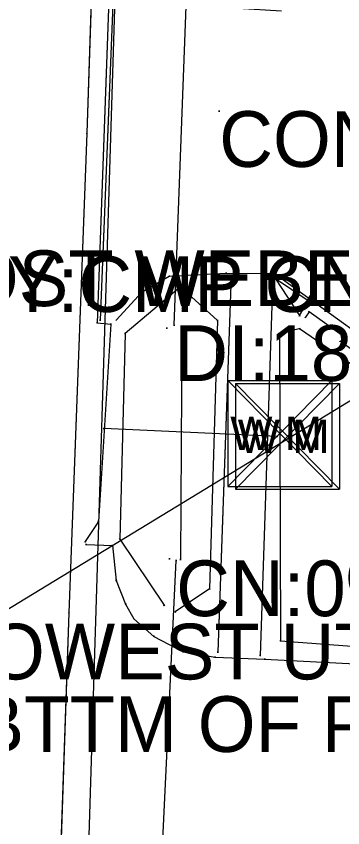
# Model space of a CAD drawing. Extents: x -99999 to 591807, y -99999 to 347168.
# Drawn here: x 591252.1 to 591281.4, y 320523.7 to 320596.6 of the extents above; entities that cross this region are included whole.
import ezdxf

# ---------------------------------------------------------------- set-up
doc = ezdxf.new("R2010")
doc.units = 0
for name, color, linetype in [('S_BREAKLINE', 7, 'Continuous'), ('S_CURB', 7, 'Continuous'), ('S_DITCHLINE', 7, 'Continuous'), ('S_DRG_PT_SYM', 7, 'Continuous'), ('S_DRIVEWAY', 7, 'Continuous'), ('S_EDGE_CONCRETE', 7, 'Continuous'), ('S_EDGE_PAVEMENT', 7, 'Continuous'), ('S_ELECTRIC_UTILITIES_ANNOT', 7, 'Continuous'), ('S_FENCE_ANNOT', 7, 'Continuous'), ('S_GRD_PT_SYM', 7, 'Continuous'), ('S_MSC_PT_SYM', 7, 'Continuous'), ('S_PARKING', 7, 'Continuous'), ('S_RDW_PT_SYM', 7, 'Continuous'), ('S_SHOULDER', 7, 'Continuous'), ('S_SIDE_DRAIN', 7, 'Continuous'), ('S_SIDE_DRAIN_ANNOT', 7, 'Continuous'), ('S_SIDEWALK', 7, 'Continuous'), ('S_SURVEY_TEXT_ANNOT', 7, 'Continuous'), ('S_UTL_PT_SYM', 7, 'Continuous'), ('S_WATER_UTILITIES', 7, 'Continuous')]:
    doc.layers.add(name, color=color, linetype=linetype)

msp = doc.modelspace()

# ---------------------------------------------------------------- linework, layer by layer
at = {"layer": 'S_BREAKLINE'}
for points in [[(591266.839, 320572.285), (591261.882, 320568.086), (591261.392, 320549.643), (591265.367, 320543.692)], [(591266.839, 320572.285), (591270.168, 320569.252), (591269.438, 320545.156), (591266.363, 320543.095)], [(591392.216, 320558.69), (591356.086, 320560.306), (591322.995, 320561.907), (591285.524, 320563.047), (591277.542, 320568.519), (591275.731, 320568.114), (591275.832, 320540.511), (591286.618, 320539.681), (591297.842, 320540.2), (591300.027, 320556.655), (591345.447, 320554.744), (591401.345, 320551.999)]]:
    msp.add_lwpolyline(points, dxfattribs=at)
at = {"layer": 'S_CURB'}
for points in [[(591281.353, 320567.898), (591278.386, 320570.023), (591278.072, 320569.548)], [(591281.353, 320567.898), (591278.386, 320570.023), (591278.072, 320569.548)], [(591407.479, 320558.411), (591363.839, 320560.323), (591322.914, 320562.301), (591285.893, 320563.966), (591281.187, 320567.394)], [(591407.479, 320558.411), (591385.659, 320559.367), (591363.839, 320560.323), (591343.376, 320561.312), (591322.914, 320562.301), (591304.404, 320563.134), (591285.893, 320563.966), (591281.187, 320567.394)], [(591407.501, 320558.912), (591363.862, 320560.823), (591322.937, 320562.802), (591286.066, 320564.459), (-99999, -99999)]]:
    msp.add_lwpolyline(points, dxfattribs=at)
at = {"layer": 'S_DITCHLINE'}
msp.add_lwpolyline([(591266.954, 320568.142), (591266.834, 320547.806)], dxfattribs=at)
msp.add_lwpolyline([(591266.954, 320568.142), (591266.834, 320547.806)], dxfattribs=at)
at = {"layer": 'S_DRG_PT_SYM'}
for points in [[(591266.286, 320568.827), (591266.286, 320568.877), (591266.286, 320568.827), (591266.236, 320568.827), (591266.286, 320568.827), (591266.286, 320568.777), (591266.286, 320568.827), (591266.336, 320568.827)], [(591266.449, 320547.719), (591266.449, 320547.769), (591266.449, 320547.719), (591266.399, 320547.719), (591266.449, 320547.719), (591266.449, 320547.669), (591266.449, 320547.719), (591266.499, 320547.719)]]:
    msp.add_lwpolyline(points, dxfattribs=at)
at = {"layer": 'S_DRIVEWAY'}
for points in [[(591275.923, 320597.03), (591271.994, 320597.253), (591266.956, 320597.82), (591264.475, 320599.333), (591263.245, 320601.023), (591262.616, 320602.121), (591260.941, 320602.14), (591259.624, 320569.278)], [(591275.923, 320597.03), (591271.994, 320597.253), (591266.956, 320597.82), (591264.475, 320599.333), (591263.245, 320601.023), (591262.616, 320602.121), (591260.941, 320602.14), (591260.282, 320585.709), (591259.624, 320569.278)], [(591261.069, 320569.288), (591263.4, 320571.823), (591265.823, 320573.221), (591270.933, 320573.516), (591275.152, 320573.478)], [(591261.069, 320569.288), (591263.4, 320571.823), (591265.823, 320573.221), (591270.933, 320573.516), (591275.152, 320573.478)], [(591258.362, 320549.144), (591260.745, 320549.059), (591261.061, 320545.933), (591261.907, 320543.789), (591262.648, 320542.475), (591264.456, 320540.899), (591267.082, 320539.519), (591269.942, 320539.026), (591274.417, 320538.861), (591285.436, 320538.297)], [(591258.362, 320549.144), (591260.745, 320549.059), (591261.061, 320545.933), (591261.907, 320543.789), (591262.648, 320542.475), (591264.456, 320540.899), (591267.082, 320539.519), (591269.942, 320539.026), (591274.417, 320538.861), (591285.436, 320538.297)]]:
    msp.add_lwpolyline(points, dxfattribs=at)
at = {"layer": 'S_EDGE_CONCRETE'}
msp.add_lwpolyline([(591275.36, 320573.004), (591277.536, 320569.699), (591278.31, 320571.012), (591275.36, 320573.004)], dxfattribs=at)
msp.add_lwpolyline([(591275.36, 320573.004), (591277.536, 320569.699), (591278.31, 320571.012)], close=True, dxfattribs=at)
at = {"layer": 'S_EDGE_PAVEMENT'}
for points in [[(591276.464, 321095.169), (591275.056, 321053.597), (591273.291, 321005.346), (591272, 320957.38), (591270.852, 320912.706), (591269.626, 320868.123), (591267.967, 320823.163), (591266.366, 320784.972), (591264.567, 320741.355), (591263.052, 320704.522), (591261.343, 320660.719), (591259.642, 320623.868), (591258.44, 320586.063), (591256.824, 320543.024), (591255.332, 320500.726), (591253.745, 320460.208), (591252.238, 320423.96)], [(591259.041, 320604.965), (591258.44, 320586.063), (591257.632, 320564.544), (591256.824, 320543.024), (591256.078, 320521.875), (591255.332, 320500.726), (591254.539, 320480.467), (591253.745, 320460.208), (591252.991, 320442.084), (591252.238, 320423.96)]]:
    msp.add_lwpolyline(points, dxfattribs=at)
at = {"layer": 'S_GRD_PT_SYM'}
for points in [[(591266.839, 320572.285), (591266.871, 320572.247), (591266.839, 320572.285), (591266.877, 320572.317), (591266.839, 320572.285), (591266.807, 320572.323), (591266.839, 320572.285), (591266.801, 320572.253)], [(591266.839, 320572.285), (591266.873, 320572.322), (591266.839, 320572.285), (591266.802, 320572.319), (591266.839, 320572.285), (591266.805, 320572.248), (591266.839, 320572.285), (591266.876, 320572.251)], [(591270.168, 320569.252), (591270.218, 320569.25), (591270.168, 320569.252), (591270.17, 320569.302), (591270.168, 320569.252), (591270.118, 320569.253), (591270.168, 320569.252), (591270.167, 320569.202)], [(591265.604, 320568.574), (591265.604, 320568.624), (591265.604, 320568.574), (591265.554, 320568.574), (591265.604, 320568.574), (591265.604, 320568.524), (591265.604, 320568.574), (591265.654, 320568.574)], [(591277.542, 320568.519), (591277.553, 320568.47), (591277.542, 320568.519), (591277.59, 320568.53), (591277.542, 320568.519), (591277.531, 320568.568), (591277.542, 320568.519), (591277.493, 320568.508)], [(591261.882, 320568.086), (591261.932, 320568.084), (591261.882, 320568.086), (591261.883, 320568.136), (591261.882, 320568.086), (591261.832, 320568.087), (591261.882, 320568.086), (591261.88, 320568.036)], [(591266.954, 320568.142), (591267.004, 320568.142), (591266.954, 320568.142), (591266.954, 320568.192), (591266.954, 320568.142), (591266.904, 320568.142), (591266.954, 320568.142), (591266.954, 320568.092)], [(591275.731, 320568.114), (591275.781, 320568.114), (591275.731, 320568.114), (591275.731, 320568.164), (591275.731, 320568.114), (591275.682, 320568.114), (591275.731, 320568.114), (591275.732, 320568.064)], [(591261.392, 320549.643), (591261.434, 320549.671), (591261.392, 320549.643), (591261.365, 320549.685), (591261.392, 320549.643), (591261.351, 320549.616), (591261.392, 320549.643), (591261.42, 320549.602)], [(591265.845, 320547.877), (591265.845, 320547.927), (591265.845, 320547.877), (591265.795, 320547.877), (591265.845, 320547.877), (591265.845, 320547.827), (591265.845, 320547.877), (591265.895, 320547.877)], [(591266.834, 320547.806), (591266.884, 320547.806), (591266.834, 320547.806), (591266.834, 320547.856), (591266.834, 320547.806), (591266.784, 320547.807), (591266.834, 320547.806), (591266.834, 320547.756)], [(591269.438, 320545.156), (591269.466, 320545.115), (591269.438, 320545.156), (591269.48, 320545.184), (591269.438, 320545.156), (591269.41, 320545.198), (591269.438, 320545.156), (591269.397, 320545.128)], [(591265.367, 320543.692), (591265.408, 320543.72), (591265.367, 320543.692), (591265.339, 320543.734), (591265.367, 320543.692), (591265.325, 320543.664), (591265.367, 320543.692), (591265.395, 320543.651)], [(591266.363, 320543.095), (591266.391, 320543.053), (591266.363, 320543.095), (591266.404, 320543.123), (591266.363, 320543.095), (591266.335, 320543.137), (591266.363, 320543.095), (591266.321, 320543.067)], [(591275.832, 320540.511), (591275.835, 320540.561), (591275.832, 320540.511), (591275.782, 320540.515), (591275.832, 320540.511), (591275.828, 320540.461), (591275.832, 320540.511), (591275.881, 320540.507)]]:
    msp.add_lwpolyline(points, close=True, dxfattribs=at)
at = {"layer": 'S_MSC_PT_SYM'}
msp.add_lwpolyline([(591270.318, 320588.044), (591270.318, 320588.094), (591270.318, 320588.044), (591270.268, 320588.044), (591270.318, 320588.044), (591270.318, 320587.994), (591270.318, 320588.044), (591270.368, 320588.044)], dxfattribs=at)
for points in [[(591271.385, 320573.331), (591271.435, 320573.329), (591271.385, 320573.331), (591271.387, 320573.381), (591271.385, 320573.331), (591271.335, 320573.333), (591271.385, 320573.331), (591271.383, 320573.281)], [(591275.128, 320573.267), (591275.177, 320573.265), (591275.128, 320573.267), (591275.129, 320573.317), (591275.128, 320573.267), (591275.078, 320573.269), (591275.128, 320573.267), (591275.126, 320573.217)], [(591275.449, 320573.327), (591275.42, 320573.287), (591275.449, 320573.327), (591275.49, 320573.298), (591275.449, 320573.327), (591275.479, 320573.368), (591275.449, 320573.327), (591275.409, 320573.356)], [(591270.191, 320539.488), (591270.241, 320539.486), (591270.191, 320539.488), (591270.193, 320539.538), (591270.191, 320539.488), (591270.141, 320539.49), (591270.191, 320539.488), (591270.189, 320539.438)], [(591274.006, 320539.192), (591274.056, 320539.19), (591274.006, 320539.192), (591274.008, 320539.242), (591274.006, 320539.192), (591273.956, 320539.193), (591274.006, 320539.192), (591274.005, 320539.142)]]:
    msp.add_lwpolyline(points, close=True, dxfattribs=at)
at = {"layer": 'S_PARKING'}
for points in [[(591407.979, 320559.722), (591364.006, 320561.845), (591322.955, 320563.708), (591286.426, 320565.418), (591275.449, 320573.327)], [(591407.979, 320559.722), (591385.992, 320560.784), (591364.006, 320561.845), (591343.48, 320562.776), (591322.955, 320563.708), (591304.691, 320564.563), (591286.426, 320565.418), (591275.449, 320573.327)]]:
    msp.add_lwpolyline(points, dxfattribs=at)
at = {"layer": 'S_RDW_PT_SYM'}
for points in [[(591258.44, 320586.063), (591258.49, 320586.061), (591258.44, 320586.063), (591258.442, 320586.113), (591258.44, 320586.063), (591258.39, 320586.065), (591258.44, 320586.063), (591258.438, 320586.013)], [(591265.823, 320573.221), (591265.82, 320573.271), (591265.823, 320573.221), (591265.773, 320573.218), (591265.823, 320573.221), (591265.826, 320573.171), (591265.823, 320573.221), (591265.873, 320573.224)], [(591270.933, 320573.516), (591270.934, 320573.566), (591270.933, 320573.516), (591270.883, 320573.517), (591270.933, 320573.516), (591270.933, 320573.466), (591270.933, 320573.516), (591270.983, 320573.516)], [(591275.152, 320573.478), (591275.152, 320573.528), (591275.152, 320573.478), (591275.102, 320573.479), (591275.152, 320573.478), (591275.151, 320573.428), (591275.152, 320573.478), (591275.201, 320573.478)], [(591275.36, 320573.004), (591275.36, 320573.054), (591275.36, 320573.004), (591275.31, 320573.004), (591275.36, 320573.004), (591275.36, 320572.954), (591275.36, 320573.004), (591275.41, 320573.004)], [(591275.36, 320573.004), (591275.333, 320572.963), (591275.36, 320573.004), (591275.402, 320572.976), (591275.36, 320573.004), (591275.388, 320573.046), (591275.36, 320573.004), (591275.319, 320573.032)], [(591275.36, 320573.004), (591275.402, 320573.032), (591275.36, 320573.004), (591275.333, 320573.046), (591275.36, 320573.004), (591275.319, 320572.977), (591275.36, 320573.004), (591275.388, 320572.962)], [(591263.4, 320571.823), (591263.375, 320571.866), (591263.4, 320571.823), (591263.356, 320571.798), (591263.4, 320571.823), (591263.425, 320571.78), (591263.4, 320571.823), (591263.443, 320571.848)], [(591278.31, 320571.012), (591278.31, 320571.062), (591278.31, 320571.012), (591278.26, 320571.012), (591278.31, 320571.012), (591278.31, 320570.962), (591278.31, 320571.012), (591278.36, 320571.012)], [(591278.31, 320571.012), (591278.282, 320570.971), (591278.31, 320571.012), (591278.351, 320570.984), (591278.31, 320571.012), (591278.338, 320571.053), (591278.31, 320571.012), (591278.268, 320571.04)], [(591278.386, 320570.023), (591278.427, 320569.995), (591278.386, 320570.023), (591278.413, 320570.065), (591278.386, 320570.023), (591278.344, 320570.05), (591278.386, 320570.023), (591278.358, 320569.981)], [(591259.624, 320569.278), (591259.674, 320569.276), (591259.624, 320569.278), (591259.626, 320569.328), (591259.624, 320569.278), (591259.574, 320569.28), (591259.624, 320569.278), (591259.622, 320569.228)], [(591261.069, 320569.288), (591261.033, 320569.322), (591261.069, 320569.288), (591261.036, 320569.251), (591261.069, 320569.288), (591261.106, 320569.254), (591261.069, 320569.288), (591261.103, 320569.325)], [(591277.536, 320569.699), (591277.536, 320569.749), (591277.536, 320569.699), (591277.486, 320569.699), (591277.536, 320569.699), (591277.536, 320569.649), (591277.536, 320569.699), (591277.586, 320569.699)], [(591277.536, 320569.699), (591277.493, 320569.724), (591277.536, 320569.699), (591277.51, 320569.656), (591277.536, 320569.699), (591277.579, 320569.674), (591277.536, 320569.699), (591277.561, 320569.742)], [(591278.072, 320569.548), (591278.113, 320569.52), (591278.072, 320569.548), (591278.099, 320569.59), (591278.072, 320569.548), (591278.03, 320569.575), (591278.072, 320569.548), (591278.044, 320569.506)], [(591259.362, 320569.055), (591259.368, 320569.105), (591259.362, 320569.055), (591259.313, 320569.06), (591259.362, 320569.055), (591259.357, 320569.005), (591259.362, 320569.055), (591259.412, 320569.05)], [(591260.591, 320568.928), (591260.641, 320568.925), (591260.591, 320568.928), (591260.595, 320568.978), (591260.591, 320568.928), (591260.542, 320568.931), (591260.591, 320568.928), (591260.588, 320568.878)], [(591281.353, 320567.898), (591281.324, 320567.857), (591281.353, 320567.898), (591281.394, 320567.869), (591281.353, 320567.898), (591281.382, 320567.938), (591281.353, 320567.898), (591281.312, 320567.927)], [(591281.187, 320567.394), (591281.157, 320567.353), (591281.187, 320567.394), (591281.227, 320567.364), (591281.187, 320567.394), (591281.216, 320567.434), (591281.187, 320567.394), (591281.146, 320567.423)], [(591259.469, 320551.213), (591259.511, 320551.185), (591259.469, 320551.213), (591259.497, 320551.254), (591259.469, 320551.213), (591259.428, 320551.24), (591259.469, 320551.213), (591259.442, 320551.171)], [(591258.286, 320549.415), (591258.328, 320549.388), (591258.286, 320549.415), (591258.314, 320549.457), (591258.286, 320549.415), (591258.245, 320549.443), (591258.286, 320549.415), (591258.259, 320549.374)], [(591258.362, 320549.144), (591258.364, 320549.194), (591258.362, 320549.144), (591258.312, 320549.146), (591258.362, 320549.144), (591258.361, 320549.094), (591258.362, 320549.144), (591258.412, 320549.143)], [(591260.745, 320549.059), (591260.794, 320549.064), (591260.745, 320549.059), (591260.739, 320549.109), (591260.745, 320549.059), (591260.695, 320549.054), (591260.745, 320549.059), (591260.75, 320549.01)], [(591261.061, 320545.933), (591261.107, 320545.952), (591261.061, 320545.933), (591261.042, 320545.98), (591261.061, 320545.933), (591261.014, 320545.915), (591261.061, 320545.933), (591261.079, 320545.887)], [(591261.907, 320543.789), (591261.95, 320543.814), (591261.907, 320543.789), (591261.882, 320543.833), (591261.907, 320543.789), (591261.863, 320543.765), (591261.907, 320543.789), (591261.931, 320543.746)], [(591256.824, 320543.024), (591256.874, 320543.022), (591256.824, 320543.024), (591256.826, 320543.074), (591256.824, 320543.024), (591256.774, 320543.026), (591256.824, 320543.024), (591256.822, 320542.974)], [(591262.648, 320542.475), (591262.68, 320542.513), (591262.648, 320542.475), (591262.61, 320542.508), (591262.648, 320542.475), (591262.615, 320542.437), (591262.648, 320542.475), (591262.685, 320542.442)], [(591264.456, 320540.899), (591264.479, 320540.943), (591264.456, 320540.899), (591264.412, 320540.922), (591264.456, 320540.899), (591264.433, 320540.855), (591264.456, 320540.899), (591264.5, 320540.876)], [(591267.082, 320539.519), (591267.09, 320539.568), (591267.082, 320539.519), (591267.033, 320539.527), (591267.082, 320539.519), (591267.073, 320539.47), (591267.082, 320539.519), (591267.131, 320539.51)], [(591269.942, 320539.026), (591269.944, 320539.076), (591269.942, 320539.026), (591269.892, 320539.028), (591269.942, 320539.026), (591269.94, 320538.976), (591269.942, 320539.026), (591269.992, 320539.024)], [(591274.417, 320538.861), (591274.42, 320538.911), (591274.417, 320538.861), (591274.368, 320538.863), (591274.417, 320538.861), (591274.415, 320538.811), (591274.417, 320538.861), (591274.467, 320538.858)]]:
    msp.add_lwpolyline(points, close=True, dxfattribs=at)
at = {"layer": 'S_SHOULDER'}
for points in [[(591264.024, 320660.547), (591262.233, 320623.511), (591261.51, 320602.347), (591260.561, 320602.272), (591259.362, 320569.055), (591260.591, 320568.928), (591259.469, 320551.213), (591258.286, 320549.415)], [(591264.024, 320660.547), (591263.128, 320642.029), (591262.233, 320623.511), (591261.51, 320602.347), (591260.561, 320602.272), (591259.961, 320585.664), (591259.362, 320569.055), (591260.591, 320568.928), (591259.469, 320551.213), (591258.286, 320549.415)]]:
    msp.add_lwpolyline(points, dxfattribs=at)
at = {"layer": 'S_SIDE_DRAIN'}
for p, q in [((591266.286, 320568.827), (591267.532, 320602.015)), ((591264.514, 320506.702), (591266.449, 320547.719))]:
    msp.add_line(p, q, dxfattribs=at)
at = {"layer": 'S_SIDEWALK'}
for points in [[(591271.385, 320573.331), (591270.191, 320539.488)], [(591271.385, 320573.331), (591270.788, 320556.409), (591270.191, 320539.488)], [(591275.128, 320573.267), (591274.006, 320539.192)], [(591275.128, 320573.267), (591274.567, 320556.229), (591274.006, 320539.192)]]:
    msp.add_lwpolyline(points, dxfattribs=at)
at = {"layer": 'S_UTL_PT_SYM'}
for points in [[(591259.939, 320559.562), (591259.939, 320559.612), (591259.939, 320559.562), (591259.889, 320559.562), (591259.939, 320559.562), (591259.939, 320559.512), (591259.939, 320559.562), (591259.989, 320559.562)], [(591275.511, 320558.855), (591275.511, 320558.905), (591275.511, 320558.855), (591275.461, 320558.855), (591275.511, 320558.855), (591275.511, 320558.805), (591275.511, 320558.855), (591275.561, 320558.855)]]:
    msp.add_lwpolyline(points, dxfattribs=at)
at = {"layer": 'S_WATER_UTILITIES'}
for p, q in [((591262.693, 320654.847), (591256.284, 320448.599)), ((591271.104, 320563.858), (591280.443, 320563.858)), ((591271.104, 320563.858), (591271.104, 320554.364)), ((591271.104, 320563.858), (591280.443, 320554.364)), ((591280.443, 320563.858), (591271.104, 320554.364)), ((591271.78, 320563.597), (591281.119, 320563.597)), ((591271.78, 320563.597), (591271.78, 320554.103)), ((591271.78, 320563.597), (591281.119, 320554.103)), ((591281.119, 320563.597), (591271.78, 320554.103)), ((591280.443, 320563.858), (591280.443, 320554.364)), ((591281.119, 320563.597), (591281.119, 320554.103)), ((591275.511, 320558.855), (591259.939, 320559.562)), ((591271.104, 320554.364), (591280.443, 320554.364)), ((591271.78, 320554.103), (591281.119, 320554.103))]:
    msp.add_line(p, q, dxfattribs=at)

# ---------------------------------------------------------------- texts
at = {"layer": 'S_ELECTRIC_UTILITIES_ANNOT'}
msp.add_text('LOWEST UTILITY LINE', height=5, dxfattribs=at).set_placement((591245.733, 320537.039))
at = {"layer": 'S_FENCE_ANNOT'}
msp.add_text('METAL POST WEBED NET,POOR', height=5, dxfattribs=at).set_placement((591218.492, 320570.546))
at = {"layer": 'S_SIDE_DRAIN_ANNOT'}
for s, p in [('DI:18" TY:CMP CN:20% BTTM OF PI', (591227.047, 320570.022)), ('DI:18" TY:CMP CN:0% BTTM OF PIP', (591266.286, 320563.827)), ('CN:0% BTTM OF PIPE', (591266.449, 320542.719)), ('CN:0% BTTM OF PIPE', (591225.295, 320530.531))]:
    msp.add_text(s, height=5, dxfattribs=at).set_placement(p)
at = {"layer": 'S_SURVEY_TEXT_ANNOT'}
msp.add_text('CONC DW TO PK', height=5, dxfattribs=at).set_placement((591270.318, 320583.044))
at = {"layer": 'S_WATER_UTILITIES'}
for p in [(591271.309, 320557.624), (591271.985, 320557.363)]:
    msp.add_text('W M', height=3, rotation=360, dxfattribs=at).set_placement(p)

doc.saveas('drawing.dxf')
